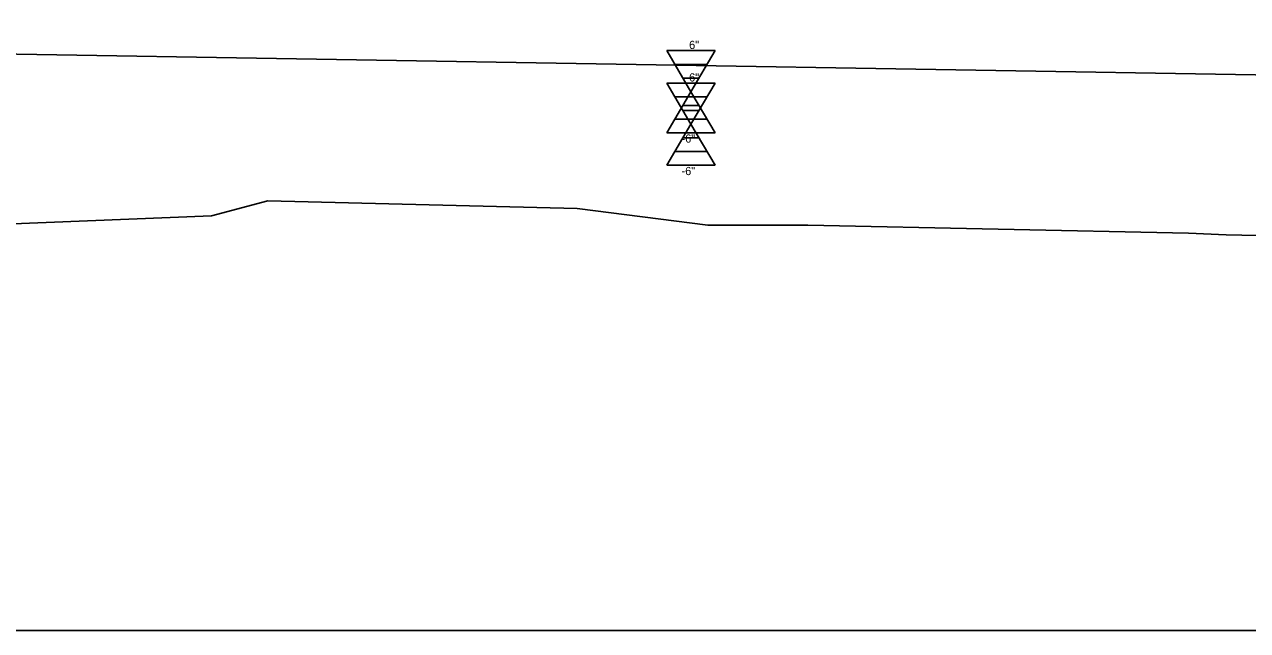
# Model space of a CAD drawing. Extents: x 573468 to 580768, y -57414 to -51768.
# Drawn here: x 575474.6 to 575549.1, y -53098.5 to -53061.6 of the extents above; entities that cross this region are included whole.
import ezdxf

# ---------------------------------------------------------------- set-up
doc = ezdxf.new("R2010")
doc.units = 0
for name, color, linetype in [('Exist Profile Cell', 7, 'Continuous'), ('Exist Vertical Profile Ground Line', 7, 'Continuous'), ('Pattern 2', 7, 'Continuous'), ('Prop Vertical Profile Grade', 7, 'Continuous'), ('Scratch_Level_0', 7, 'Continuous')]:
    doc.layers.add(name, color=color, linetype=linetype)

msp = doc.modelspace()

# ---------------------------------------------------------------- linework, layer by layer
at = {"layer": 'Exist Profile Cell'}
msp.add_line((573765.214, -53098.544), (577467.911, -53098.544), dxfattribs=at)
at = {"layer": 'Exist Vertical Profile Ground Line'}
msp.add_lwpolyline([(575383.373, -53078.127), (575404.609, -53074.624), (575407.123, -53074.03), (575407.639, -53074.037), (575436.502, -53075.083), (575437.51, -53075.12), (575439.301, -53075.097), (575467.13, -53073.968), (575468.334, -53073.981), (575485.999, -53073.271), (575489.425, -53072.371), (575508.269, -53072.837), (575516.25, -53073.855), (575517.968, -53073.841), (575522.346, -53073.849), (575545.535, -53074.336), (575547.838, -53074.437), (575552.641, -53074.536)], dxfattribs=at)
at = {"layer": 'Pattern 2'}
for p, q in [((575513.748, -53065.194), (575516.68, -53065.194)), ((575513.748, -53065.194), (575515.214, -53067.694)), ((575515.214, -53067.694), (575516.68, -53065.194)), ((575514.236, -53066.028), (575516.191, -53066.028)), ((575514.725, -53066.861), (575515.703, -53066.861)), ((575513.748, -53070.194), (575515.214, -53067.694)), ((575515.214, -53067.694), (575516.68, -53070.194)), ((575514.725, -53068.528), (575515.703, -53068.528)), ((575514.236, -53069.361), (575516.191, -53069.361)), ((575513.748, -53070.194), (575516.68, -53070.194))]:
    msp.add_line(p, q, dxfattribs=at)
at = {"layer": 'Prop Vertical Profile Grade'}
msp.add_line((575365.214, -53061.619), (575695.214, -53067.094), dxfattribs=at)
at = {"layer": 'Scratch_Level_0'}
for p, q in [((575513.748, -53063.214), (575516.68, -53063.214)), ((575513.748, -53063.214), (575515.214, -53065.714)), ((575515.214, -53065.714), (575516.68, -53063.214)), ((575514.236, -53064.048), (575516.191, -53064.048)), ((575514.725, -53064.881), (575515.703, -53064.881)), ((575513.748, -53068.214), (575515.214, -53065.714)), ((575515.214, -53065.714), (575516.68, -53068.214)), ((575514.725, -53066.548), (575515.703, -53066.548)), ((575514.236, -53067.381), (575516.191, -53067.381)), ((575513.748, -53068.214), (575516.68, -53068.214))]:
    msp.add_line(p, q, dxfattribs=at)

# ---------------------------------------------------------------- texts
at = {"layer": 'Pattern 2'}
for s, p in [('6"', (575515.101, -53065.093)), ('-6"', (575514.64, -53070.797))]:
    msp.add_text(s, height=0.5, rotation=360, dxfattribs=at).set_placement(p)
at = {"layer": 'Scratch_Level_0'}
for s, p in [('6"', (575515.101, -53063.113)), ('-6"', (575514.64, -53068.817))]:
    msp.add_text(s, height=0.5, dxfattribs=at).set_placement(p)

doc.saveas('drawing.dxf')
